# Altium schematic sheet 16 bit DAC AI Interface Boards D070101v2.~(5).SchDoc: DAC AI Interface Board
size B; Engineer: J. Heefner; DocumentNumber: D070101; Revision: 01; SheetNumber: 1; SheetTotal: 1; PageSetup: Record=PageOptions¦CenterHorizontal=True¦CenterVertical=True¦PrintScale=1.12¦XCorrection=1.00¦YCorrection=1.00¦PrintKind=0¦BorderSize=5000000¦LeftOffset=0¦BottomOffset=0¦Orientation=2¦PaperLength=1000¦PaperWidth=1000¦Scale=100¦PaperSource=15¦PrintQuality=1200¦MediaType=1¦DitherType=10¦PaperKind=Tabloid¦PrintScaleMode=1
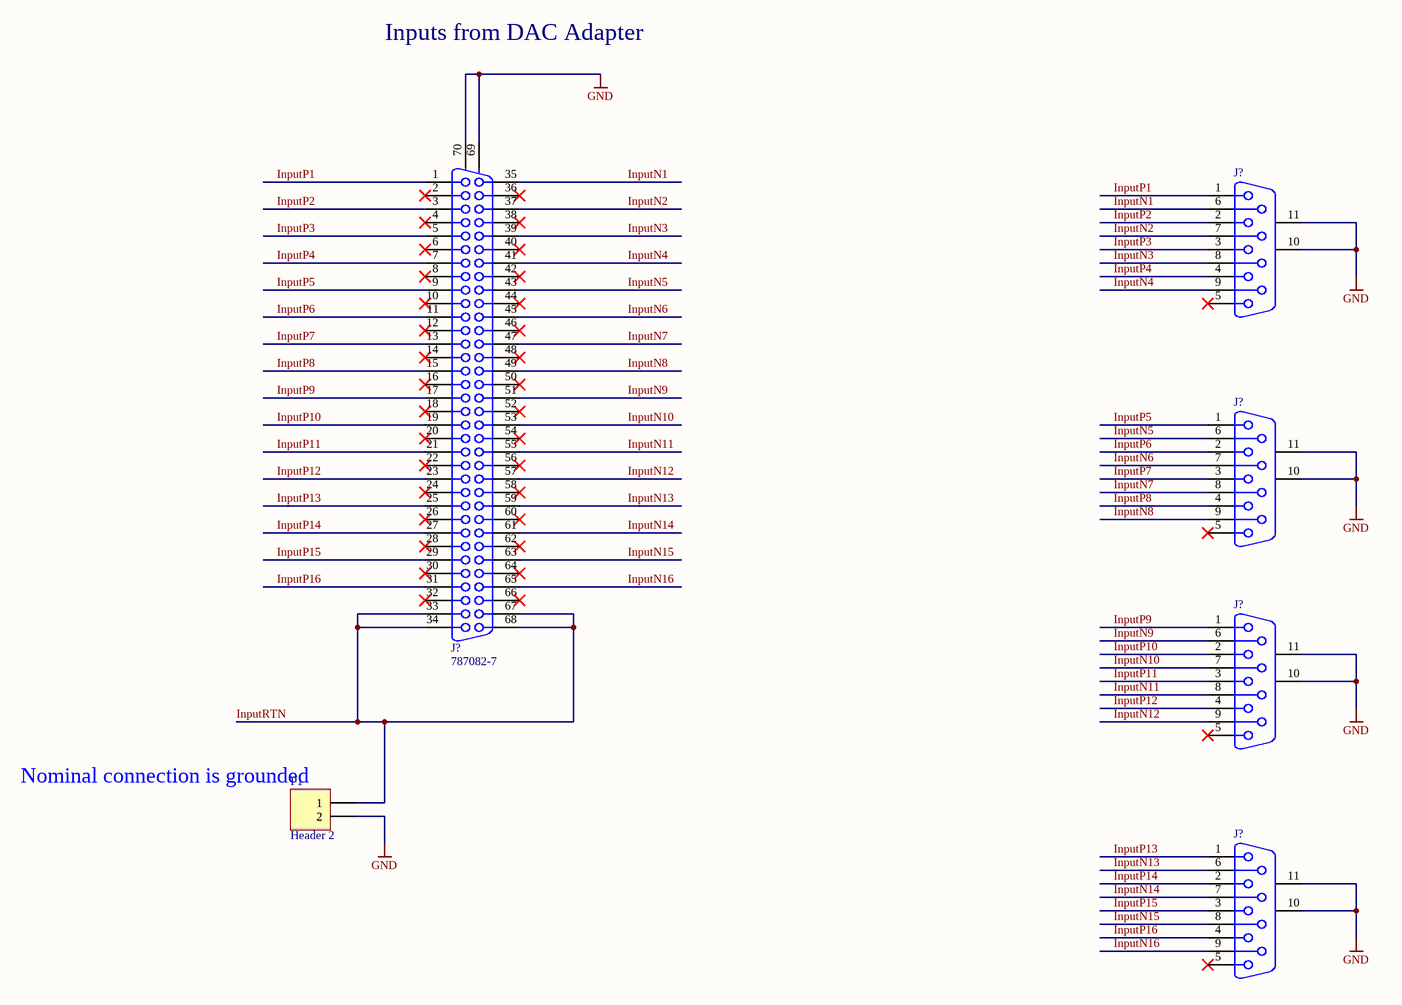
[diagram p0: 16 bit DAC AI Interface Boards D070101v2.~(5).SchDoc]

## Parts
(Parts that share a designator on the sheet are numbered #1, #2 ... from top to bottom, then left to right.)
J?#1  787082-7  [787082-7]
J?#2  D9F 90deg  [D9F 90DEG]  (value not drawn)
J?#3  D9F 90deg  [D9F 90DEG]  (value not drawn)
J?#4  D9F 90deg  [D9F 90DEG]  (value not drawn)
J?#5  D9F 90deg  [D9F 90DEG]  (value not drawn)
P1  Header 2  [HDR1X2]

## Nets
GND: J?#1.69(MH1) J?#1.70(MH2) J?#2.10(MH1) J?#2.11(MH2) J?#3.10(MH1) J?#3.11(MH2) J?#4.10(MH1) J?#4.11(MH2) J?#5.10(MH1) J?#5.11(MH2) P1.2
InputN1: J?#1.35 J?#2.6
InputN2: J?#1.37 J?#2.7
InputN3: J?#1.39 J?#2.8
InputN4: J?#1.41 J?#2.9
InputN5: J?#1.43 J?#3.6
InputN6: J?#1.45 J?#3.7
InputN7: J?#1.47 J?#3.8
InputN8: J?#1.49 J?#3.9
InputN9: J?#1.51 J?#4.6
InputN10: J?#1.53 J?#4.7
InputN11: J?#1.55 J?#4.8
InputN12: J?#1.57 J?#4.9
InputN13: J?#1.59 J?#5.6
InputN14: J?#1.61 J?#5.7
InputN15: J?#1.63 J?#5.8
InputN16: J?#1.65 J?#5.9
InputP1: J?#1.1 J?#2.1
InputP2: J?#1.3 J?#2.2
InputP3: J?#1.5 J?#2.3
InputP4: J?#1.7 J?#2.4
InputP5: J?#1.9 J?#3.1
InputP6: J?#1.11 J?#3.2
InputP7: J?#1.13 J?#3.3
InputP8: J?#1.15 J?#3.4
InputP9: J?#1.17 J?#4.1
InputP10: J?#1.19 J?#4.2
InputP11: J?#1.21 J?#4.3
InputP12: J?#1.23 J?#4.4
InputP13: J?#1.25 J?#5.1
InputP14: J?#1.27 J?#5.2
InputP15: J?#1.29 J?#5.3
InputP16: J?#1.31 J?#5.4
InputRTN: J?#1.33 J?#1.34 J?#1.67 J?#1.68 P1.1

Not connected (* = marked no-connect by the designer): J?#1 2* 4* 6* 8* 10* 12* 14* 16* 18* 20* 22* 24* 26* 28* 30* 32* 36* 38* 40* 42* 44* 46* 48* 50* 52* 54* 56* 58* 60* 62* 64* 66*; J?#2 5*; J?#3 5*; J?#4 5*; J?#5 5*

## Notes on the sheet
- Inputs from DAC Adapter
- (near P1) Nominal connection is grounded

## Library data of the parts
J?#1 = D68F 90deg: CONN D-TYPE RCPT 68POS R/A SLDR; Manufacturer: TE Connectivity; Manufacturer Part Number: 7870827; Plating: Bright,Copper; Voltage Rating: 30V; Current Rating: 1A; Gender: Female; Number of Positions: 68; Connector Type: Receptacle,Connector; Number of Ports: 1; Shielding: Shielded; Mating Alignment: No (Without); Mating Connector Lock: Yes (With); PCB Mount Retention: With; PCB Mounting Orientation: Right Angle; Pitch: 0.05inch; PCB Thickness: 1.57mm; Contact Post Length: 0.1inch; Hole Diameter: 0.109inch; Approvals: UL
J?#2-J?#5 = D9F 90deg: 9 Position D-Sub Receptacle, Female Sockets Connector; Manufacturer: TE Connectivity; Manufacturer Part Number: 5747844-4; Plating: Tin; Body Material: Metal; Voltage Rating: 125V; Current Rating: 6A; Number of Positions: 9; Number of Ports: 1; Mating Connector Lock: Yes (With); PCB Mount Retention: With; PCB Mounting Orientation: Right Angle; Preloaded: Yes; Sealable: No (Without); Pitch: 0.108inch; PCB Thickness: 1.58mm; Contact Post Length: 0.125inch; Hole Diameter: 3.18mm; Approvals: UL,CSA
P1 = Header 2: Header, 2-Pin; Manufacturer: Molex; Number of Positions: 2; Gender: Male; Contact Resistance: 10mR; Max Current Rating: 4A; Voltage Rating: 250V; Insulation Resistance: 500GR; Pitch: 2.54mm; Approvals: UL,CSA; Glow Wire Compliant: Non-compliant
